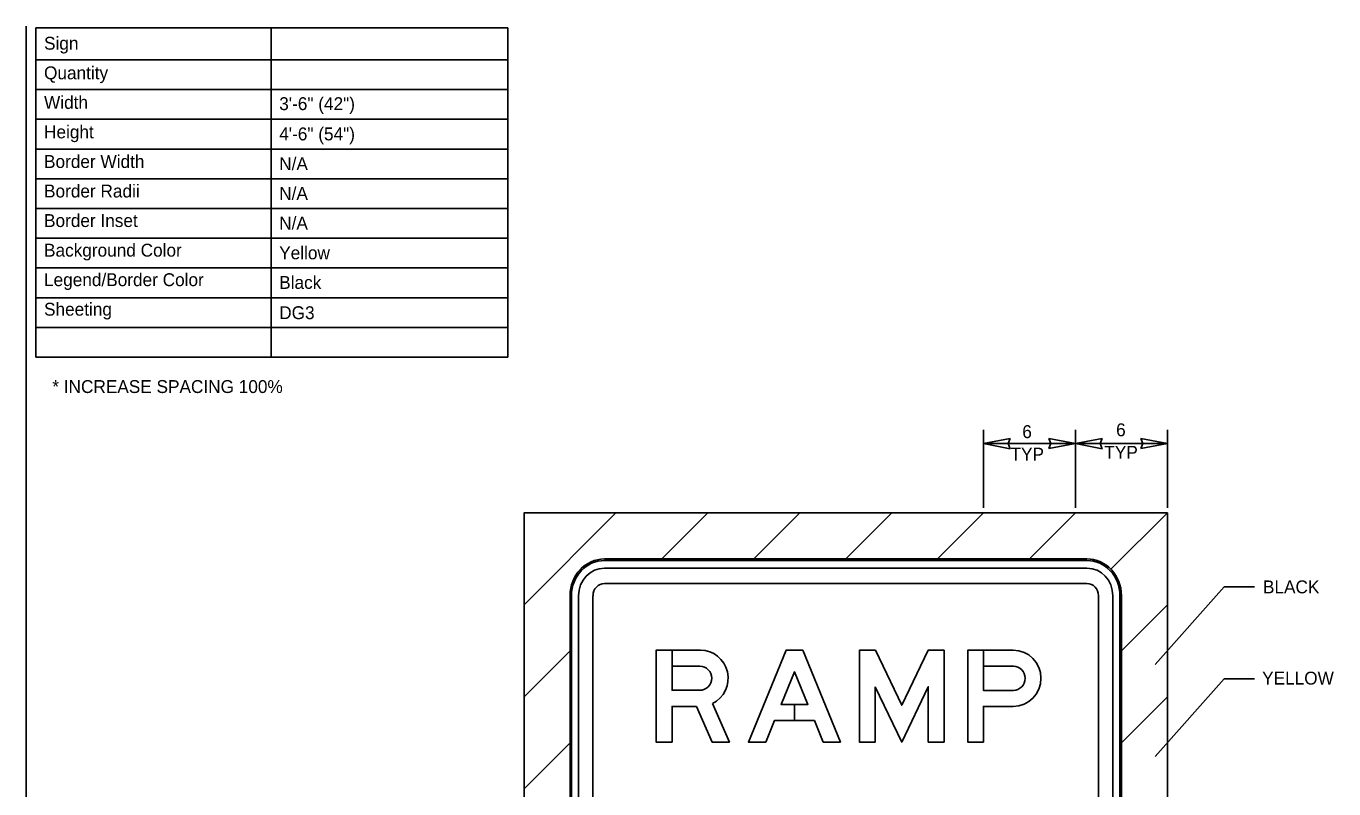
# Model space of a CAD drawing. Extents: x 582908 to 586040, y 1530940 to 1533040.
# Drawn here: x 584558 to 585981, y 1532211 to 1533040 of the extents above; entities that cross this region are included whole.
import ezdxf

# ---------------------------------------------------------------- set-up
doc = ezdxf.new("R2010")
doc.units = 0
for name, color, linetype in [('GSDims', 7, 'Continuous'), ('SheetLinesMisc2_dp', 7, 'Continuous'), ('SignPanel', 7, 'Continuous'), ('TextMisc', 7, 'Continuous'), ('TextNotes', 7, 'Continuous'), ('TextShtNo', 7, 'Continuous')]:
    doc.layers.add(name, color=color, linetype=linetype)

msp = doc.modelspace()

# ---------------------------------------------------------------- linework, layer by layer
at = {"layer": 'GSDims'}
for p, q in [((585600.1, 1532516.2), (585600.1, 1532600.9)), ((585700.1, 1532516.2), (585700.1, 1532600.9)), ((585800.1, 1532516.2), (585800.1, 1532600.9)), ((585629.1, 1532591.3), (585600.1, 1532585.9)), ((585600.1, 1532585.9), (585700.1, 1532585.9)), ((585600.1, 1532585.9), (585629.1, 1532580.3)), ((585626.9, 1532585.9), (585629.1, 1532591.3)), ((585629.1, 1532580.3), (585626.9, 1532585.9)), ((585700.1, 1532585.9), (585671.1, 1532591.5)), ((585671.1, 1532591.5), (585673.3, 1532585.9)), ((585673.3, 1532585.9), (585671.1, 1532580.5)), ((585671.1, 1532580.5), (585700.1, 1532585.9)), ((585729.1, 1532591.3), (585700.1, 1532585.9)), ((585700.1, 1532585.9), (585800.1, 1532585.9)), ((585700.1, 1532585.9), (585729.1, 1532580.3)), ((585726.9, 1532585.9), (585729.1, 1532591.3)), ((585729.1, 1532580.3), (585726.9, 1532585.9)), ((585800.1, 1532585.9), (585771.1, 1532591.5)), ((585771.1, 1532591.5), (585773.3, 1532585.9)), ((585773.3, 1532585.9), (585771.1, 1532580.5)), ((585771.1, 1532580.5), (585800.1, 1532585.9)), ((585786.8, 1532345.6), (585861.9, 1532430)), ((585861.9, 1532430), (585895, 1532430)), ((585786.8, 1532245.6), (585861.9, 1532330)), ((585861.9, 1532330), (585895, 1532330))]:
    msp.add_line(p, q, dxfattribs=at)
at = {"layer": 'SheetLinesMisc2_dp'}
for p, q in [((584558.3, 1533039.8), (584558.3, 1531119.8)), ((584569, 1532679.9), (584569, 1533037.8)), ((584569, 1533037.8), (585082.3, 1533037.8)), ((584824.9, 1533037.8), (584824.9, 1532679.9)), ((585082.3, 1533037.8), (585082.3, 1532679.9)), ((584569, 1533003.3), (585082.3, 1533003.3)), ((584569, 1532970.9), (585082.3, 1532970.9)), ((584569, 1532938.6), (585082.3, 1532938.6)), ((584569, 1532906.2), (585082.3, 1532906.2)), ((584569, 1532873.9), (585082.3, 1532873.9)), ((584569, 1532841.6), (585082.3, 1532841.6)), ((584569, 1532809.2), (585082.3, 1532809.2)), ((584569, 1532776.9), (585082.3, 1532776.9)), ((584569, 1532744.5), (585082.3, 1532744.5)), ((584569, 1532712.2), (585082.3, 1532712.2)), ((584569, 1532679.9), (585082.3, 1532679.9))]:
    msp.add_line(p, q, dxfattribs=at)
at = {"layer": 'SignPanel'}
for p, q in [((585200.1, 1532510.5), (585100.1, 1532510.5)), ((585712.6, 1532460.5), (585187.6, 1532460.5)), ((585187.6, 1532458.9), (585187.6, 1532458.8)), ((585712.6, 1532458.8), (585187.6, 1532458.8)), ((585712.6, 1532450.5), (585187.6, 1532450.5)), ((585712.6, 1532458.8), (585712.6, 1532458.9)), ((585712.6, 1532433.9), (585187.6, 1532433.9)), ((585150.1, 1532420.5), (585150.1, 1531700.6)), ((585150.1, 1532420.5), (585150.1, 1531700.6)), ((585151.6, 1532420.5), (585151.6, 1531700.6)), ((585151.6, 1532420.5), (585151.7, 1532420.5)), ((585159.5, 1532420.5), (585159.5, 1531700.6)), ((585175.1, 1532420.5), (585175.1, 1531700.6)), ((585725.1, 1531700.6), (585725.1, 1532420.5)), ((585740.7, 1531700.6), (585740.7, 1532420.5)), ((585748.5, 1532420.5), (585748.5, 1532420.5)), ((585748.5, 1531700.6), (585748.5, 1532420.5)), ((585750.1, 1531700.6), (585750.1, 1532420.5)), ((585291.4, 1532317.7), (585261.1, 1532317.7)), ((585632.5, 1532317.6), (585600, 1532317.6)), ((585600, 1532300.1), (585632.4, 1532300.1))]:
    msp.add_line(p, q, dxfattribs=at)
for points in [[(585200.1, 1532510.5), (585100.1, 1532510.5), (585100.1, 1532410.6), (585200.1, 1532510.5)], [(585250.1, 1532460.5), (585350.1, 1532460.5), (585400.1, 1532510.5), (585300.1, 1532510.5), (585250.1, 1532460.5)], [(585450.1, 1532460.5), (585550.1, 1532460.5), (585600.1, 1532510.5), (585500.1, 1532510.5), (585450.1, 1532460.5)], [(585738.7, 1532449.2), (585800.1, 1532510.5), (585700.1, 1532510.5), (585650.1, 1532460.5), (585712.6, 1532460.5)], [(585750.1, 1532360.5), (585750.1, 1532260.5), (585800.1, 1532310.5), (585800.1, 1532410.5), (585750.1, 1532360.5)], [(585100.1, 1532310.6), (585100.1, 1532210.6), (585150.1, 1532260.6), (585150.1, 1532360.6), (585100.1, 1532310.6)], [(585292, 1532361.3), (585243.8, 1532361.3), (585243.8, 1532261.3), (585261.1, 1532261.3), (585261.1, 1532300.2), (585287.6, 1532300.2)], [(585291.4, 1532317.7), (585261.1, 1532317.7), (585261.1, 1532361.3), (585243.8, 1532361.3), (585243.8, 1532261.3)], [(585291.4, 1532317.7), (585261.1, 1532317.7), (585261.1, 1532361.3), (585243.8, 1532361.3), (585243.8, 1532261.3)], [(585292, 1532361.3), (585261.1, 1532361.3), (585261.1, 1532343.8), (585291.4, 1532343.8)], [(585292, 1532361.3), (585261.1, 1532361.3), (585261.1, 1532343.8), (585291.4, 1532343.8)], [(585632.4, 1532361.3), (585582.8, 1532361.3), (585582.8, 1532261.3), (585600, 1532261.3), (585600, 1532300.1)], [(585600, 1532361.3), (585582.8, 1532361.3), (585582.8, 1532261.3), (585600, 1532261.3), (585600, 1532300.1), (585632.4, 1532300.1)], [(585600, 1532361.3), (585582.8, 1532361.3), (585582.8, 1532261.3), (585600, 1532261.3), (585600, 1532300.1), (585632.4, 1532300.1)], [(585632.4, 1532361.3), (585600, 1532361.3), (585600, 1532343.8), (585632.5, 1532343.8)], [(585632.5, 1532317.6), (585600, 1532317.6), (585600, 1532361.3)], [(585632.4, 1532361.3), (585600, 1532361.3), (585600, 1532343.8), (585632.5, 1532343.8)], [(585632.5, 1532317.6), (585600, 1532317.6), (585600, 1532361.3)], [(585261.1, 1532317.7), (585261.1, 1532343.8), (585291.4, 1532343.8)], [(585600, 1532317.6), (585600, 1532343.8), (585632.5, 1532343.8)], [(585243.8, 1532261.3), (585261.1, 1532261.3), (585261.1, 1532300.2), (585287.6, 1532300.2), (585304.7, 1532261.3), (585323.6, 1532261.3), (585305.2, 1532303.3)], [(585243.8, 1532261.3), (585261.1, 1532261.3), (585261.1, 1532300.2), (585287.6, 1532300.2), (585304.7, 1532261.3), (585323.6, 1532261.3), (585305.2, 1532303.3)], [(585287.6, 1532300.2), (585304.7, 1532261.3), (585323.6, 1532261.3), (585305.2, 1532303.3)]]:
    msp.add_lwpolyline(points, dxfattribs=at)
for points in [[(585100.1, 1532510.5), (585800.1, 1532510.5), (585800.1, 1531610.6), (585100.1, 1531610.6)], [(585416, 1532284.9), (585425.7, 1532261.3), (585444.3, 1532261.3), (585403.4, 1532361.3), (585385.2, 1532361.3), (585344.3, 1532261.3), (585363, 1532261.3), (585372.7, 1532284.9)], [(585372.7, 1532284.9), (585394.3, 1532284.9), (585394.3, 1532302.4), (585379.8, 1532302.4), (585394.3, 1532337.9), (585408.9, 1532302.4), (585394.3, 1532302.4), (585394.3, 1532284.9), (585416, 1532284.9), (585425.7, 1532261.3), (585444.3, 1532261.3), (585403.4, 1532361.3), (585385.2, 1532361.3), (585344.3, 1532261.3), (585363, 1532261.3)], [(585372.7, 1532284.9), (585394.3, 1532284.9), (585394.3, 1532302.4), (585379.8, 1532302.4), (585394.3, 1532337.9), (585408.9, 1532302.4), (585394.3, 1532302.4), (585394.3, 1532284.9), (585416, 1532284.9), (585425.7, 1532261.3), (585444.3, 1532261.3), (585403.4, 1532361.3), (585385.2, 1532361.3), (585344.3, 1532261.3), (585363, 1532261.3)], [(585482.3, 1532321.6), (585511.1, 1532261.3), (585539.9, 1532321.6), (585539.9, 1532261.3), (585557.1, 1532261.3), (585557.1, 1532361.3), (585539.8, 1532361.3), (585511.1, 1532301.4), (585482.4, 1532361.3), (585465, 1532361.3), (585465, 1532261.3), (585482.3, 1532261.3)], [(585482.3, 1532321.6), (585511.1, 1532261.3), (585539.9, 1532321.6), (585539.9, 1532261.3), (585557.1, 1532261.3), (585557.1, 1532361.3), (585539.8, 1532361.3), (585511.1, 1532301.4), (585482.4, 1532361.3), (585465, 1532361.3), (585465, 1532261.3), (585482.3, 1532261.3)], [(585482.3, 1532321.6), (585511.1, 1532261.3), (585539.9, 1532321.6), (585539.9, 1532261.3), (585557.1, 1532261.3), (585557.1, 1532361.3), (585539.8, 1532361.3), (585511.1, 1532301.4), (585482.4, 1532361.3), (585465, 1532361.3), (585465, 1532261.3), (585482.3, 1532261.3)], [(585394.3, 1532337.9), (585408.9, 1532302.4), (585379.8, 1532302.4)]]:
    msp.add_lwpolyline(points, close=True, dxfattribs=at)
for centre, major_axis, ratio, start_param, end_param in [((585187.6, 1532420.5), (0, 40), 0.937555, 0, 1.570796), ((585187.6, 1532420.5), (0, 40), 0.937555, 0, 1.570796), ((585187.6, 1532420.5), (0, 38.3), 0.937555, 0, 1.570796), ((585187.6, 1532420.5), (0, 30), 0.937555, 0, 1.570796), ((585712.6, 1532420.5), (0, 40), 0.937555, 4.712389, 6.283185), ((585712.6, 1532420.5), (0, 40), 0.937555, 5.51114, 6.283185), ((585712.6, 1532420.5), (0, 40), 0.937555, 4.712389, 6.283185), ((585712.6, 1532420.5), (0, 38.3), 0.937555, 4.712389, 6.283185), ((585712.6, 1532420.5), (0, 30), 0.937555, 4.712389, 6.283185), ((585187.6, 1532420.5), (0, 13.3), 0.937555, 0, 1.570796), ((585712.6, 1532420.5), (0, 13.3), 0.937555, 4.712389, 6.283185), ((585292, 1532330.8), (0, 30.6), 0.985, 3.595687, 6.283185), ((585292, 1532330.8), (0, 30.6), 0.985, 3.595687, 6.283185), ((585292, 1532330.8), (0, 30.6), 0.985, 3.595687, 6.283185), ((585632.4, 1532330.7), (0, 30.6), 0.985, 3.141593, 6.283185), ((585632.4, 1532330.7), (0, 30.6), 0.985, 3.141593, 6.283185), ((585632.4, 1532330.7), (0, 30.6), 0.985, 3.141593, 6.283185), ((585291.4, 1532330.8), (0, 13.1), 0.985, 3.141593, 6.283185), ((585291.4, 1532330.8), (0, 13.1), 0.985, 3.141593, 6.283185), ((585291.4, 1532330.8), (0, 13.1), 0.985, 3.141593, 6.283185), ((585632.5, 1532330.7), (0, 13.1), 0.985, 3.141593, 6.283185), ((585632.5, 1532330.7), (0, 13.1), 0.985, 3.141593, 6.283185), ((585632.5, 1532330.7), (0, 13.1), 0.985, 3.141593, 6.283185)]:
    msp.add_ellipse(centre, major_axis=major_axis, ratio=ratio, start_param=start_param, end_param=end_param, dxfattribs=at)

# ---------------------------------------------------------------- texts
at = {"layer": 'GSDims'}
for s, p in [('6', (585744.3, 1532593.9)), ('6', (585642.2, 1532591.9)), ('TYP', (585629.4, 1532567.4)), ('TYP', (585731.5, 1532569.4)), ('BLACK', (585904.1, 1532423.1)), ('YELLOW', (585903.2, 1532323.9))]:
    msp.add_text(s, height=14, dxfattribs=at).set_placement(p)
at = {"layer": 'TextMisc'}
for s, p in [('Sign', (584577.8, 1533014.2)), ('Quantity', (584577.8, 1532982)), ('Width', (584577.8, 1532949.9)), ('Height', (584577.8, 1532917.8)), ('Border Width', (584577.8, 1532885.6)), ('Border Radii', (584577.8, 1532853.5)), ('Border Inset', (584577.8, 1532821.4)), ('Background Color', (584577.8, 1532789.2)), ('Legend/Border Color', (584577.8, 1532757.1)), ('Sheeting', (584577.8, 1532725))]:
    msp.add_text(s, height=14, dxfattribs=at).set_placement(p)
at = {"layer": 'TextNotes'}
msp.add_text('* INCREASE SPACING 100%', height=14, dxfattribs=at).set_placement((584586.8, 1532640.9))
at = {"layer": 'TextShtNo'}
for s, p in [('3\'-6" (42")', (584833.7, 1532948.5)), ('4\'-6" (54")', (584833.7, 1532915.6)), ('N/A', (584833.7, 1532883.2)), ('N/A', (584833.7, 1532850.9)), ('N/A', (584833.7, 1532818.6)), ('Yellow', (584833.7, 1532786.3)), ('Black', (584833.7, 1532754.1)), ('DG3', (584833.7, 1532721.2))]:
    msp.add_text(s, height=14, dxfattribs=at).set_placement(p)

doc.saveas('drawing.dxf')
